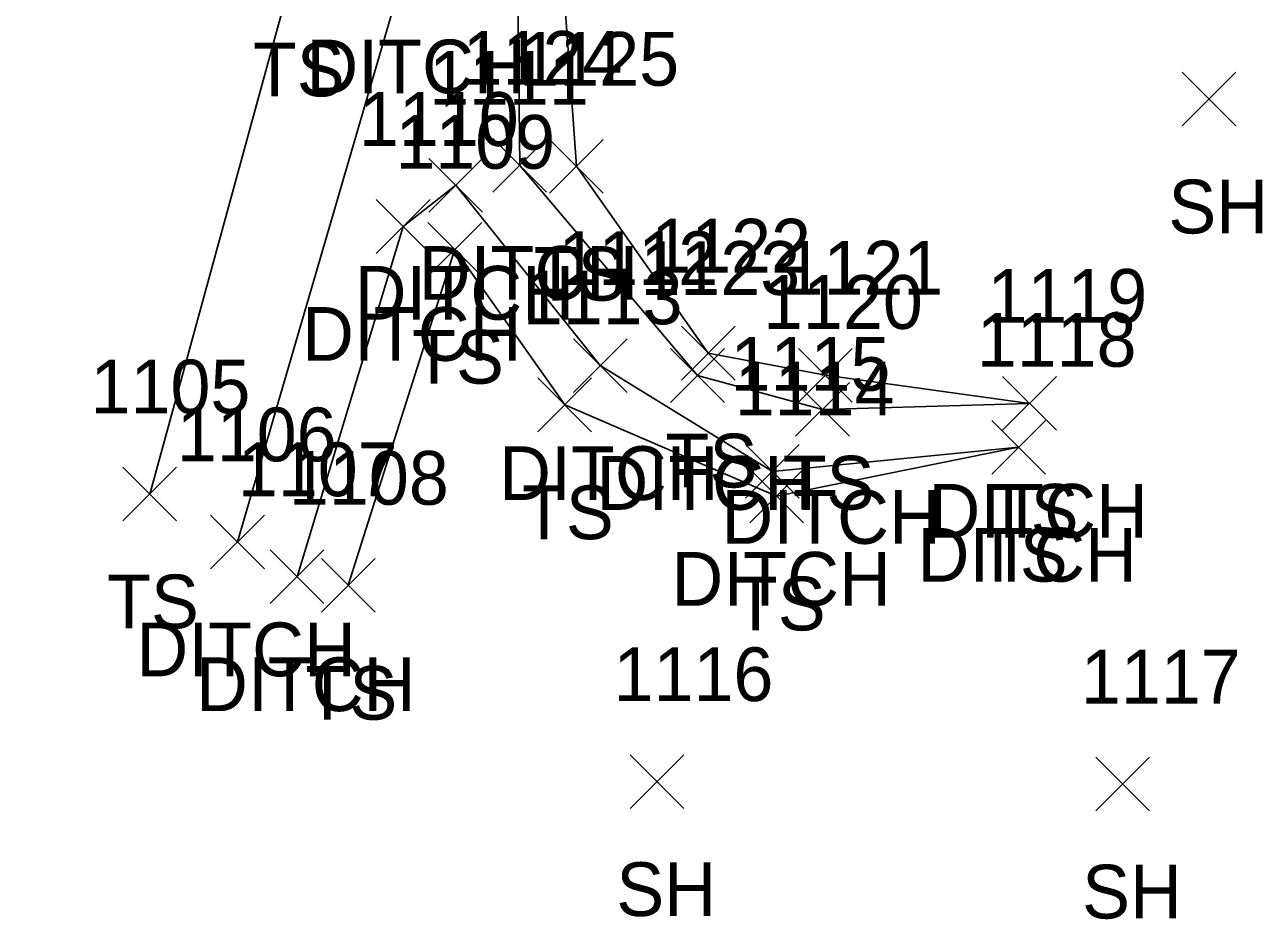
# Model space of a CAD drawing. Extents: x 1514253 to 1516033, y 782541 to 785002.
# Drawn here: x 1515320.47 to 1515366.55, y 782587.08 to 782620.37 of the extents above; entities that cross this region are included whole.
import ezdxf

# ---------------------------------------------------------------- set-up
doc = ezdxf.new("R2010")
doc.units = 0
for name, color, linetype in [('D_A', 7, 'Continuous'), ('D_I', 7, 'Continuous'), ('D_TIC', 7, 'Continuous'), ('DD', 7, 'Continuous'), ('L_A', 7, 'Continuous'), ('L_I', 7, 'Continuous'), ('L_TIC', 7, 'Continuous'), ('LELB', 7, 'Continuous')]:
    doc.layers.add(name, color=color, linetype=linetype)

msp = doc.modelspace()

# ---------------------------------------------------------------- linework, layer by layer
at = {"layer": 'D_TIC'}
for points in [[(1515337.903, 782614.134), (1515339.903, 782616.134)], [(1515339.903, 782614.134), (1515337.903, 782616.134)], [(1515335.519, 782613.393), (1515337.519, 782615.393)], [(1515337.519, 782613.393), (1515335.519, 782615.393)], [(1515333.562, 782611.86), (1515335.562, 782613.86)], [(1515335.562, 782611.86), (1515333.562, 782613.86)], [(1515340.899, 782606.68), (1515342.899, 782608.68)], [(1515342.899, 782606.68), (1515340.899, 782608.68)], [(1515344.522, 782606.313), (1515346.522, 782608.313)], [(1515346.522, 782606.313), (1515344.522, 782608.313)], [(1515356.883, 782605.277), (1515358.883, 782607.277)], [(1515358.883, 782605.277), (1515356.883, 782607.277)], [(1515349.175, 782605.05), (1515351.175, 782607.05)], [(1515351.175, 782605.05), (1515349.175, 782607.05)], [(1515356.478, 782603.641), (1515358.478, 782605.641)], [(1515358.478, 782603.641), (1515356.478, 782605.641)], [(1515347.312, 782602.746), (1515349.312, 782604.746)], [(1515349.312, 782602.746), (1515347.312, 782604.746)], [(1515327.394, 782600.12), (1515329.394, 782602.12)], [(1515329.394, 782600.12), (1515327.394, 782602.12)], [(1515329.614, 782598.822), (1515331.614, 782600.822)], [(1515331.614, 782598.822), (1515329.614, 782600.822)]]:
    msp.add_lwpolyline(points, dxfattribs=at)
at = {"layer": 'DD'}
for points in [[(1515199.394, 782648.84), (1515235.483, 782648.45), (1515272.163, 782648.844), (1515285.608, 782648.488), (1515294.464, 782648.384), (1515312.17, 782640.182), (1515323.367, 782638.781), (1515329.306, 782640.309), (1515333.451, 782637.848), (1515333.036, 782633.949), (1515334.721, 782622.814), (1515328.394, 782601.12)], [(1515357.883, 782606.277), (1515350.175, 782606.05), (1515345.522, 782607.313), (1515338.903, 782615.134), (1515338.78, 782625.875), (1515340.884, 782635.592), (1515335.13, 782644.312)], [(1515330.614, 782599.822), (1515334.562, 782612.86), (1515336.519, 782614.393), (1515341.899, 782607.68), (1515348.312, 782603.746), (1515357.478, 782604.641)]]:
    msp.add_lwpolyline(points, dxfattribs=at)
at = {"layer": 'L_TIC'}
for points in [[(1515363.564, 782616.601), (1515365.564, 782618.601)], [(1515365.564, 782616.601), (1515363.564, 782618.601)], [(1515340.013, 782614.1), (1515342.013, 782616.1)], [(1515342.013, 782614.1), (1515340.013, 782616.1)], [(1515335.486, 782611.011), (1515337.486, 782613.011)], [(1515337.486, 782611.011), (1515335.486, 782613.011)], [(1515344.922, 782607.145), (1515346.922, 782609.145)], [(1515346.922, 782607.145), (1515344.922, 782609.145)], [(1515349.282, 782606.324), (1515351.282, 782608.324)], [(1515351.282, 782606.324), (1515349.282, 782608.324)], [(1515339.578, 782605.221), (1515341.578, 782607.221)], [(1515341.578, 782605.221), (1515339.578, 782607.221)], [(1515356.883, 782605.277), (1515358.883, 782607.277)], [(1515358.883, 782605.277), (1515356.883, 782607.277)], [(1515356.478, 782603.641), (1515358.478, 782605.641)], [(1515358.478, 782603.641), (1515356.478, 782605.641)], [(1515324.128, 782601.902), (1515326.128, 782603.902)], [(1515326.128, 782601.902), (1515324.128, 782603.902)], [(1515347.468, 782601.825), (1515349.468, 782603.825)], [(1515349.468, 782601.825), (1515347.468, 782603.825)], [(1515331.517, 782598.504), (1515333.517, 782600.504)], [(1515333.517, 782598.504), (1515331.517, 782600.504)], [(1515343.011, 782591.195), (1515345.011, 782593.195)], [(1515345.011, 782591.195), (1515343.011, 782593.195)], [(1515360.354, 782591.104), (1515362.354, 782593.104)], [(1515362.354, 782591.104), (1515360.354, 782593.104)]]:
    msp.add_lwpolyline(points, dxfattribs=at)
at = {"layer": 'LELB'}
for points in [[(1515267.493, 782617.708), (1515275.905, 782623.682), (1515279.076, 782634.626), (1515280.627, 782640.948), (1515290.641, 782638.315), (1515296.789, 782634.635), (1515304.473, 782631.621), (1515309.893, 782622.536), (1515316.95, 782625.103), (1515323.664, 782628.572), (1515323.948, 782631.832), (1515325.669, 782634.817), (1515329.658, 782632.505), (1515330.558, 782622.703), (1515325.128, 782602.902)], [(1515357.883, 782606.277), (1515350.282, 782607.324), (1515345.922, 782608.145), (1515341.013, 782615.1), (1515340.261, 782625.67), (1515343.846, 782635.098), (1515351.986, 782639.451), (1515360.567, 782638.564)], [(1515332.517, 782599.504), (1515336.486, 782612.011), (1515340.578, 782606.221), (1515348.468, 782602.825), (1515357.478, 782604.641)]]:
    msp.add_lwpolyline(points, dxfattribs=at)

# ---------------------------------------------------------------- texts
at = {"layer": 'D_A'}
for p in [(1515330.957, 782617.814), (1515335.139, 782610.134), (1515332.755, 782609.393), (1515330.798, 782607.86), (1515338.135, 782602.68), (1515341.758, 782602.313), (1515346.411, 782601.05), (1515354.119, 782601.277), (1515353.715, 782599.641), (1515344.549, 782598.746), (1515324.63, 782596.12), (1515326.85, 782594.822)]:
    msp.add_text('DITCH', height=2, dxfattribs=at).set_placement(p)
at = {"layer": 'D_I'}
for s, p in [('1124', (1515336.777, 782618.134)), ('1111', (1515335.527, 782617.393)), ('1110', (1515332.916, 782615.86)), ('1112', (1515340.34, 782610.68)), ('1123', (1515343.396, 782610.313)), ('1119', (1515356.316, 782609.277)), ('1120', (1515347.962, 782609.05)), ('1118', (1515355.919, 782607.641)), ('1115', (1515346.753, 782606.746)), ('1106', (1515326.134, 782604.12)), ('1107', (1515328.409, 782602.822))]:
    msp.add_text(s, height=2, dxfattribs=at).set_placement(p)
at = {"layer": 'L_A'}
for s, p in [('TS', (1515328.968, 782617.703)), ('SH', (1515363.052, 782612.601)), ('TS', (1515339.422, 782610.1)), ('TS', (1515334.896, 782607.011)), ('TS', (1515344.331, 782603.145)), ('TS', (1515348.691, 782602.324)), ('TS', (1515338.987, 782601.221)), ('TS', (1515356.292, 782601.277)), ('TS', (1515355.888, 782599.641)), ('TS', (1515323.538, 782597.902)), ('TS', (1515346.877, 782597.825)), ('TS', (1515330.926, 782594.504)), ('SH', (1515342.499, 782587.195)), ('SH', (1515359.843, 782587.104))]:
    msp.add_text(s, height=2, dxfattribs=at).set_placement(p)
at = {"layer": 'L_I'}
for s, p in [('1125', (1515338.887, 782618.1)), ('1109', (1515334.274, 782615.011)), ('1122', (1515343.796, 782611.145)), ('1121', (1515348.723, 782610.324)), ('1119', (1515356.316, 782609.277)), ('1113', (1515339.018, 782609.221)), ('1118', (1515355.919, 782607.641)), ('1105', (1515322.924, 782605.902)), ('1114', (1515346.908, 782605.825)), ('1108', (1515330.312, 782602.504)), ('1116', (1515342.397, 782595.195)), ('1117', (1515359.795, 782595.104))]:
    msp.add_text(s, height=2, dxfattribs=at).set_placement(p)

doc.saveas('drawing.dxf')
